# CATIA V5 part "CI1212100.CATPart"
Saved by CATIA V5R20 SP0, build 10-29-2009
Part number: CI1212100
Bounding box of the stored display mesh (mm): x -12 to 12, y -10.22 to 118, z -13.659 to 13.975
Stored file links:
  C:\Users\Raffaele\Desktop\3D X SITO CF\BOLEX\19-INCLINED ASSEMBLY REF_CI\CI1212100.CATPart
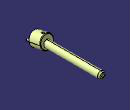
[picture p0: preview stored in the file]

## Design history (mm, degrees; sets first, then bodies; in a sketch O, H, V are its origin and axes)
Set1
  DatumSurface1 to DatumSurface16 "MANIFOLD_SOLID_BREP #380"
  DatumSurface17 to DatumSurface39 "MANIFOLD_SOLID_BREP #1097"
Body1 (main body)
